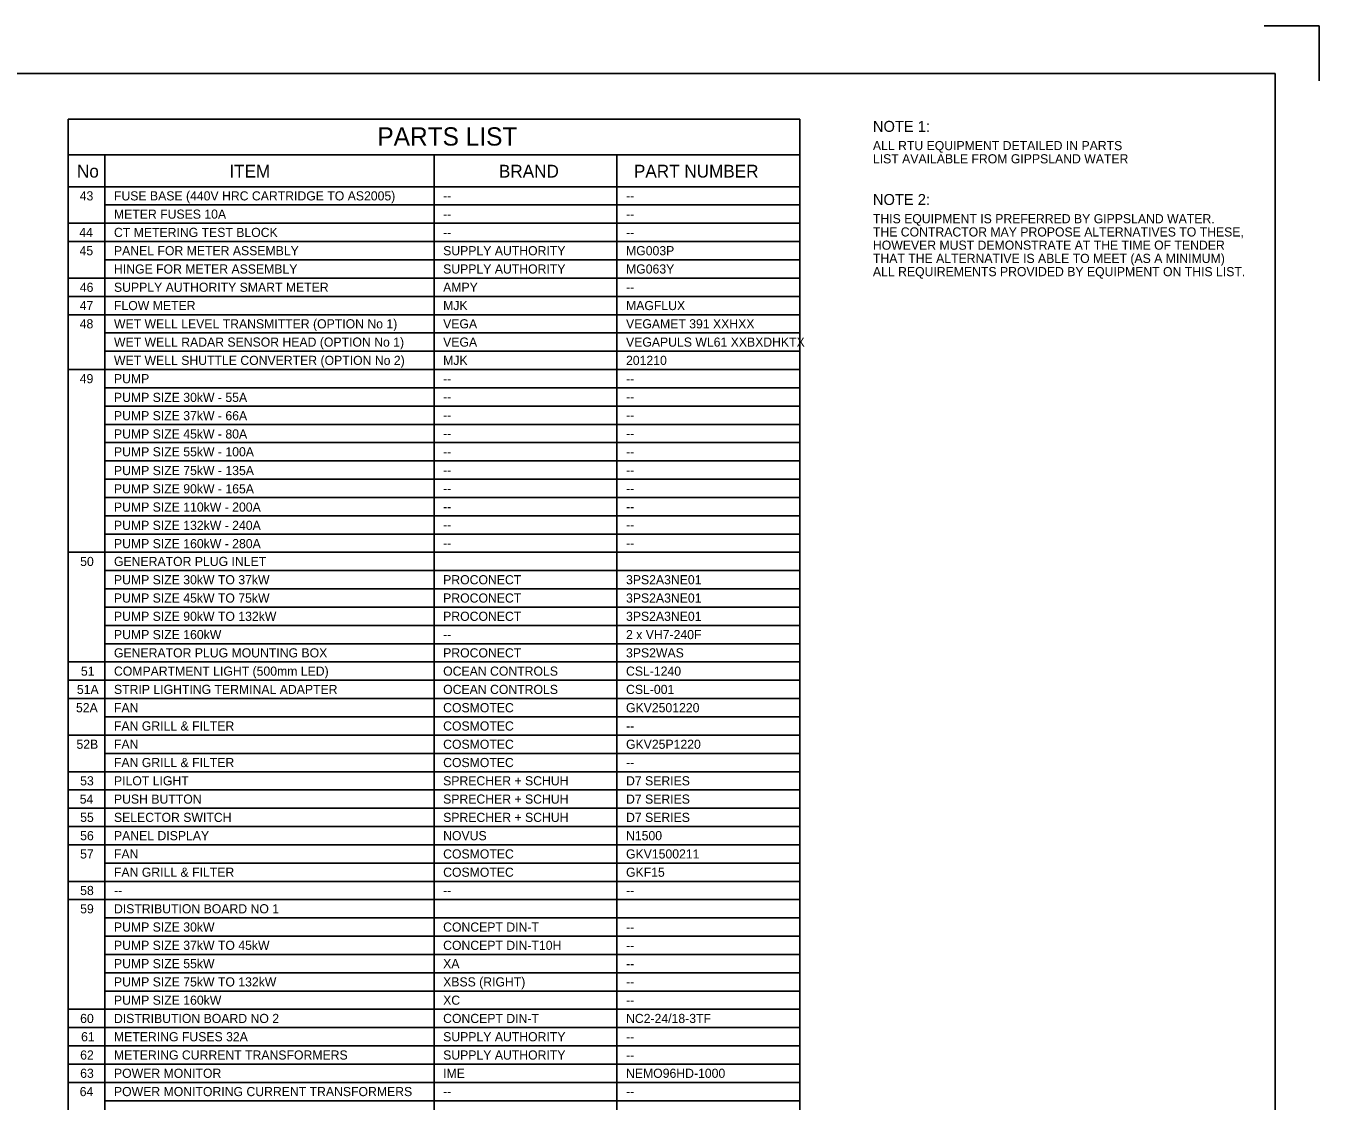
# Model space of a CAD drawing. Extents: x 841 to 1682, y 0 to 594.
# Drawn here: x 1328.4 to 1682, y 299.9 to 594 of the extents above; entities that cross this region are included whole.
import ezdxf

# ---------------------------------------------------------------- set-up
doc = ezdxf.new("R2010")
doc.units = 0
for name, color, linetype in [('A1BORDER', 7, 'Continuous'), ('BASE', 7, 'Continuous'), ('Default', 7, 'Continuous'), ('Level 1', 7, 'Continuous')]:
    doc.layers.add(name, color=color, linetype=linetype)

msp = doc.modelspace()

# ---------------------------------------------------------------- linework, layer by layer
at = {"layer": 'A1BORDER'}
for p, q in [((1667, 594), (1682, 594)), ((1682, 579), (1682, 594)), ((869, 581), (1670, 581)), ((1670, 581), (1670, 15))]:
    msp.add_line(p, q, dxfattribs=at)
at = {"layer": 'Default'}
for p, q in [((1350, 510), (1540, 510)), ((1350, 505), (1540, 505))]:
    msp.add_line(p, q, dxfattribs=at)
at = {"layer": 'Level 1'}
for p, q in [((1340, 568.5), (1340, 75)), ((1340, 568.5), (1540, 568.5)), ((1540, 75), (1540, 568.5)), ((1340, 558.75), (1540, 558.75)), ((1350, 558.75), (1350, 75)), ((1440, 558.75), (1440, 75)), ((1490, 558.75), (1490, 75)), ((1340, 550), (1540, 550)), ((1350, 545), (1540, 545)), ((1340, 540), (1540, 540)), ((1340, 535), (1540, 535)), ((1350, 530), (1540, 530)), ((1340, 525), (1540, 525)), ((1340, 520), (1540, 520)), ((1340, 515), (1540, 515)), ((1340, 500), (1540, 500)), ((1350, 495), (1540, 495)), ((1350, 490), (1540, 490)), ((1350, 485), (1540, 485)), ((1350, 480), (1540, 480)), ((1350, 475), (1540, 475)), ((1350, 470), (1540, 470)), ((1350, 465), (1540, 465)), ((1350, 460), (1540, 460)), ((1350, 455), (1540, 455)), ((1340, 450), (1540, 450)), ((1350, 445), (1540, 445)), ((1350, 440), (1540, 440)), ((1350, 435), (1540, 435)), ((1350, 430), (1540, 430)), ((1350, 425), (1540, 425)), ((1340, 420), (1540, 420)), ((1340, 415), (1540, 415)), ((1340, 410), (1540, 410)), ((1350, 405), (1540, 405)), ((1340, 400), (1540, 400)), ((1350, 395), (1540, 395)), ((1340, 390), (1540, 390)), ((1340, 385), (1540, 385)), ((1340, 380), (1540, 380)), ((1340, 375), (1540, 375)), ((1340, 370), (1540, 370)), ((1350, 365), (1540, 365)), ((1340, 360), (1540, 360)), ((1340, 355), (1540, 355)), ((1350, 350), (1540, 350)), ((1350, 345), (1540, 345)), ((1350, 340), (1540, 340)), ((1350, 335), (1540, 335)), ((1350, 330), (1540, 330)), ((1340, 325), (1540, 325)), ((1340, 320), (1540, 320)), ((1340, 315), (1540, 315)), ((1340, 310), (1540, 310)), ((1340, 305), (1540, 305)), ((1350, 300), (1540, 300))]:
    msp.add_line(p, q, dxfattribs=at)

# ---------------------------------------------------------------- texts
at = {"layer": 'BASE'}
for s, p in [('WET WELL LEVEL TRANSMITTER (OPTION No 1)', (1352.5, 511.25)), ('VEGA', (1442.5, 511.25)), ('VEGAMET 391 XXHXX', (1492.5, 511.25)), ('WET WELL RADAR SENSOR HEAD (OPTION No 1)', (1352.5, 506.25)), ('VEGA', (1442.5, 506.25)), ('VEGAPULS WL61 XXBXDHKTX', (1492.5, 506.25)), ('WET WELL SHUTTLE CONVERTER (OPTION No 2)', (1352.5, 501.25)), ('MJK', (1442.5, 501.25)), ('201210', (1492.5, 501.25))]:
    msp.add_text(s, height=2.5, dxfattribs=at).set_placement(p)
at = {"layer": 'Default'}
for s, p in [('PUMP', (1352.5, 496.25)), ('51A', (1342.365, 411.25)), ('STRIP LIGHTING TERMINAL ADAPTER', (1352.5, 411.25)), ('OCEAN CONTROLS', (1442.5, 411.25)), ('CSL-001', (1492.5, 411.25)), ('DISTRIBUTION BOARD NO 1', (1352.5, 351.25))]:
    msp.add_text(s, height=2.5, dxfattribs=at).set_placement(p)
at = {"layer": 'Level 1'}
for s, height, p in [('PARTS LIST', 5, (1424.515, 561.25)), ('NOTE 1:', 3, (1560, 565)), ('ALL RTU EQUIPMENT DETAILED IN PARTS', 2.5, (1560, 560)), ('LIST AVAILABLE FROM GIPPSLAND WATER', 2.5, (1560, 556.382)), ('No', 3.5, (1342.385, 552.5)), ('ITEM', 3.5, (1384.043, 552.5)), ('BRAND', 3.5, (1457.753, 552.5)), ('PART NUMBER', 3.5, (1494.66, 552.5)), ('43', 2.5, (1343.132, 546.25)), ('FUSE BASE (440V HRC CARTRIDGE TO AS2005)', 2.5, (1352.5, 546.25)), ('--', 2.5, (1442.5, 546.25)), ('--', 2.5, (1492.5, 546.25)), ('NOTE 2:', 3, (1560, 545)), ('METER FUSES 10A', 2.5, (1352.5, 541.25)), ('--', 2.5, (1442.5, 541.25)), ('--', 2.5, (1492.5, 541.25)), ('THIS EQUIPMENT IS PREFERRED BY GIPPSLAND WATER.', 2.5, (1560, 540)), ('44', 2.5, (1343.008, 536.25)), ('CT METERING TEST BLOCK', 2.5, (1352.5, 536.25)), ('THE CONTRACTOR MAY PROPOSE ALTERNATIVES TO THESE,', 2.5, (1560, 536.382)), ('--', 2.5, (1442.5, 536.25)), ('--', 2.5, (1492.5, 536.25)), ('HOWEVER MUST DEMONSTRATE AT THE TIME OF TENDER', 2.5, (1560, 532.764)), ('45', 2.5, (1343.089, 531.25)), ('PANEL FOR METER ASSEMBLY', 2.5, (1352.5, 531.25)), ('SUPPLY AUTHORITY', 2.5, (1442.5, 531.25)), ('MG003P', 2.5, (1492.5, 531.25)), ('THAT THE ALTERNATIVE IS ABLE TO MEET (AS A MINIMUM)', 2.5, (1560, 529.146)), ('HINGE FOR METER ASSEMBLY', 2.5, (1352.5, 526.25)), ('SUPPLY AUTHORITY', 2.5, (1442.5, 526.25)), ('MG063Y', 2.5, (1492.5, 526.25)), ('ALL REQUIREMENTS PROVIDED BY EQUIPMENT ON THIS LIST.', 2.5, (1560, 525.527)), ('46', 2.5, (1343.164, 521.25)), ('SUPPLY AUTHORITY SMART METER', 2.5, (1352.5, 521.25)), ('AMPY', 2.5, (1442.5, 521.25)), ('--', 2.5, (1492.5, 521.25)), ('47', 2.5, (1343.132, 516.25)), ('FLOW METER', 2.5, (1352.5, 516.25)), ('MJK', 2.5, (1442.5, 516.25)), ('MAGFLUX', 2.5, (1492.5, 516.25)), ('48', 2.5, (1343.132, 511.25)), ('49', 2.5, (1343.132, 496.25)), ('--', 2.5, (1442.5, 496.25)), ('--', 2.5, (1492.5, 496.25)), ('PUMP SIZE 30kW - 55A', 2.5, (1352.5, 491.125)), ('--', 2.5, (1442.5, 491.25)), ('--', 2.5, (1492.5, 491.25)), ('PUMP SIZE 37kW - 66A', 2.5, (1352.5, 486.125)), ('--', 2.5, (1442.5, 486.25)), ('--', 2.5, (1492.5, 486.25)), ('PUMP SIZE 45kW - 80A', 2.5, (1352.5, 481.125)), ('--', 2.5, (1442.5, 481.25)), ('--', 2.5, (1492.5, 481.25)), ('PUMP SIZE 55kW - 100A', 2.5, (1352.5, 476.25)), ('--', 2.5, (1442.5, 476.25)), ('--', 2.5, (1492.5, 476.25)), ('PUMP SIZE 75kW - 135A', 2.5, (1352.5, 471.125)), ('--', 2.5, (1442.5, 471.25)), ('--', 2.5, (1492.5, 471.25)), ('PUMP SIZE 90kW - 165A', 2.5, (1352.5, 466.125)), ('--', 2.5, (1442.5, 466.25)), ('--', 2.5, (1492.5, 466.25)), ('PUMP SIZE 110kW - 200A', 2.5, (1352.5, 461.125)), ('--', 2.5, (1442.5, 461.25)), ('--', 2.5, (1492.5, 461.25)), ('PUMP SIZE 132kW - 240A', 2.5, (1352.5, 456.125)), ('--', 2.5, (1442.5, 456.25)), ('--', 2.5, (1492.5, 456.25)), ('PUMP SIZE 160kW - 280A', 2.5, (1352.5, 451.125)), ('--', 2.5, (1442.5, 451.25)), ('--', 2.5, (1492.5, 451.25)), ('50', 2.5, (1343.257, 446.25)), ('GENERATOR PLUG INLET', 2.5, (1352.5, 446.25)), ('PUMP SIZE 30kW TO 37kW', 2.5, (1352.5, 441.25)), ('PROCONECT', 2.5, (1442.5, 441.25)), ('3PS2A3NE01', 2.5, (1492.5, 441.25)), ('PUMP SIZE 45kW TO 75kW', 2.5, (1352.5, 436.25)), ('PROCONECT', 2.5, (1442.5, 436.25)), ('3PS2A3NE01', 2.5, (1492.5, 436.25)), ('PUMP SIZE 90kW TO 132kW', 2.5, (1352.5, 431.25)), ('PROCONECT', 2.5, (1442.5, 431.25)), ('3PS2A3NE01', 2.5, (1492.5, 431.25)), ('PUMP SIZE 160kW', 2.5, (1352.5, 426.25)), ('2 x VH7-240F', 2.5, (1492.5, 426.25)), ('--', 2.5, (1442.5, 426.25)), ('GENERATOR PLUG MOUNTING BOX', 2.5, (1352.5, 421.25)), ('PROCONECT', 2.5, (1442.5, 421.25)), ('3PS2WAS', 2.5, (1492.5, 421.25)), ('51', 2.5, (1343.463, 416.25)), ('COMPARTMENT LIGHT (500mm LED)', 2.5, (1352.5, 416.25)), ('OCEAN CONTROLS', 2.5, (1442.5, 416.25)), ('CSL-1240', 2.5, (1492.5, 416.25)), ('52A', 2.5, (1342.116, 406.25)), ('FAN', 2.5, (1352.5, 406.25)), ('COSMOTEC', 2.5, (1442.5, 406.25)), ('GKV2501220', 2.5, (1492.5, 406.25)), ('FAN GRILL & FILTER', 2.5, (1352.5, 401.25)), ('COSMOTEC', 2.5, (1442.5, 401.25)), ('--', 2.5, (1492.5, 401.25)), ('52B', 2.5, (1342.241, 396.25)), ('FAN', 2.5, (1352.5, 396.25)), ('COSMOTEC', 2.5, (1442.5, 396.25)), ('GKV25P1220', 2.5, (1492.5, 396.25)), ('FAN GRILL & FILTER', 2.5, (1352.5, 391.25)), ('COSMOTEC', 2.5, (1442.5, 391.25)), ('--', 2.5, (1492.5, 391.25)), ('53', 2.5, (1343.257, 386.25)), ('PILOT LIGHT', 2.5, (1352.5, 386.25)), ('SPRECHER + SCHUH', 2.5, (1442.5, 386.25)), ('D7 SERIES', 2.5, (1492.5, 386.25)), ('54', 2.5, (1343.132, 381.25)), ('PUSH BUTTON', 2.5, (1352.5, 381.25)), ('SPRECHER + SCHUH', 2.5, (1442.5, 381.25)), ('D7 SERIES', 2.5, (1492.5, 381.25)), ('55', 2.5, (1343.257, 376.25)), ('SELECTOR SWITCH', 2.5, (1352.5, 376.25)), ('SPRECHER + SCHUH', 2.5, (1442.5, 376.25)), ('D7 SERIES', 2.5, (1492.5, 376.25)), ('56', 2.5, (1343.257, 371.25)), ('PANEL DISPLAY', 2.5, (1352.5, 371.25)), ('NOVUS', 2.5, (1442.5, 371.25)), ('N1500', 2.5, (1492.5, 371.25)), ('57', 2.5, (1343.237, 366.25)), ('FAN', 2.5, (1352.5, 366.25)), ('COSMOTEC', 2.5, (1442.5, 366.25)), ('GKV1500211', 2.5, (1492.5, 366.25)), ('FAN GRILL & FILTER', 2.5, (1352.5, 361.25)), ('COSMOTEC', 2.5, (1442.5, 361.25)), ('GKF15', 2.5, (1492.5, 361.25)), ('58', 2.5, (1343.257, 356.25)), ('--', 2.5, (1352.5, 356.25)), ('--', 2.5, (1442.5, 356.25)), ('--', 2.5, (1492.5, 356.25)), ('59', 2.5, (1343.257, 351.25)), ('PUMP SIZE 30kW', 2.5, (1352.5, 346.25)), ('CONCEPT DIN-T', 2.5, (1442.5, 346.25)), ('--', 2.5, (1492.5, 346.25)), ('PUMP SIZE 37kW TO 45kW', 2.5, (1352.5, 341.25)), ('CONCEPT DIN-T10H', 2.5, (1442.5, 341.25)), ('--', 2.5, (1492.5, 341.25)), ('PUMP SIZE 55kW', 2.5, (1352.5, 336.25)), ('XA', 2.5, (1442.5, 336.25)), ('--', 2.5, (1492.5, 336.25)), ('PUMP SIZE 75kW TO 132kW', 2.5, (1352.5, 331.25)), ('XBSS (RIGHT)', 2.5, (1442.5, 331.25)), ('PUMP SIZE 160kW', 2.5, (1352.5, 326.25)), ('--', 2.5, (1492.5, 331.25)), ('XC', 2.5, (1442.5, 326.25)), ('--', 2.5, (1492.5, 326.25)), ('60', 2.5, (1343.257, 321.25)), ('DISTRIBUTION BOARD NO 2', 2.5, (1352.5, 321.25)), ('CONCEPT DIN-T', 2.5, (1442.5, 321.25)), ('NC2-24/18-3TF', 2.5, (1492.5, 321.25)), ('61', 2.5, (1343.506, 316.25)), ('METERING FUSES 32A', 2.5, (1352.5, 316.25)), ('SUPPLY AUTHORITY', 2.5, (1442.5, 316.25)), ('--', 2.5, (1492.5, 316.25)), ('62', 2.5, (1343.257, 311.25)), ('METERING CURRENT TRANSFORMERS', 2.5, (1352.5, 311.25)), ('SUPPLY AUTHORITY', 2.5, (1442.5, 311.25)), ('--', 2.5, (1492.5, 311.25)), ('63', 2.5, (1343.257, 306.25)), ('POWER MONITOR', 2.5, (1352.5, 306.25)), ('IME', 2.5, (1442.5, 306.25)), ('NEMO96HD-1000', 2.5, (1492.5, 306.25)), ('64', 2.5, (1343.132, 301.25)), ('POWER MONITORING CURRENT TRANSFORMERS', 2.5, (1352.5, 301.25)), ('--', 2.5, (1442.5, 301.25)), ('--', 2.5, (1492.5, 301.25))]:
    msp.add_text(s, height=height, dxfattribs=at).set_placement(p)

doc.saveas('drawing.dxf')
